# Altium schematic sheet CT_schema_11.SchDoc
size 281 x 153 mm
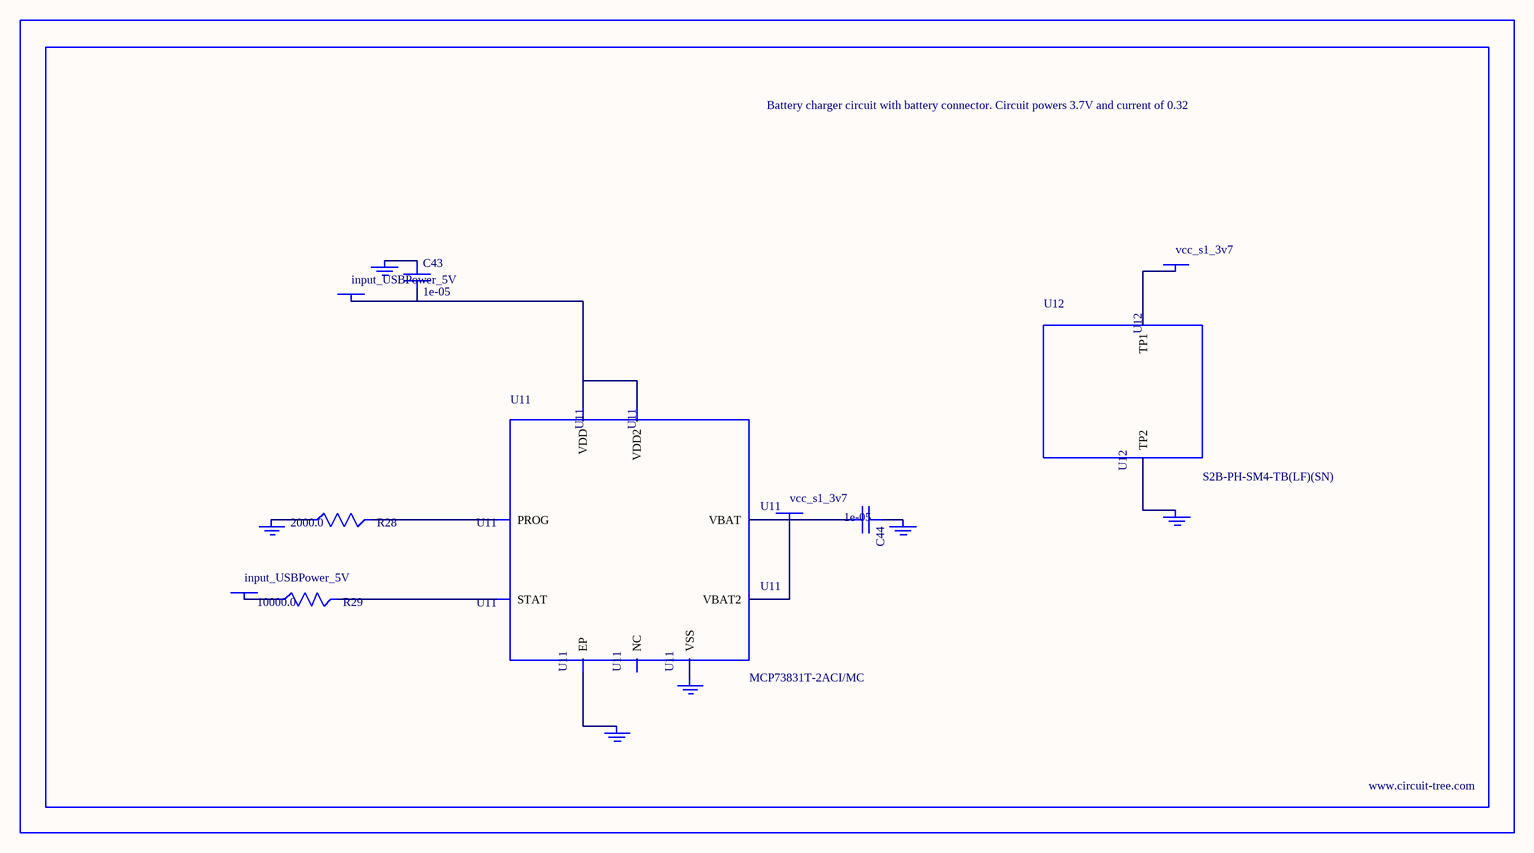
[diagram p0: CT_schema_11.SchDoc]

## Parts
BORDER10  (no value)
C43  1e-05  [C1206]
C44  1e-05  [C1206]
GND_INSTANCE_10_0  (no value)
GND_INSTANCE_10_1  (no value)
GND_INSTANCE_10_2  (no value)
GND_INSTANCE_10_3  (no value)
GND_INSTANCE_10_4  (no value)
GND_INSTANCE_10_5  (no value)
POWER_INSTANCE_10_0  input_USBPower_5V
POWER_INSTANCE_10_1  input_USBPower_5V
POWER_INSTANCE_10_2  vcc_s1_3v7
POWER_INSTANCE_10_3  vcc_s1_3v7
R28  2000.0  [R0603]
R29  10000.0  [R0603]
U11  MCP73831T-2ACI/MC  [DFN8_2X3MC]
U12  S2B-PH-SM4-TB(LF)(SN)  [JST-2-SMD]

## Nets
NetC43_1: C43.1 GND_INSTANCE_10_0.0(GND)
NetC43_2: C43.2 POWER_INSTANCE_10_0.0(PWR) U11.1(VDD) U11.2(VDD2)
NetC44_1: C44.1 GND_INSTANCE_10_1.0(GND)
NetC44_2: C44.2 POWER_INSTANCE_10_2.0(PWR) U11.3(VBAT) U11.4(VBAT2)
NetGND_INSTANCE_10_2_0: GND_INSTANCE_10_2.0(GND) R28.1
NetGND_INSTANCE_10_3_0: GND_INSTANCE_10_3.0(GND) U11.9(EP)
NetGND_INSTANCE_10_4_0: GND_INSTANCE_10_4.0(GND) U11.6(VSS)
NetGND_INSTANCE_10_5_0: GND_INSTANCE_10_5.0(GND) U12.2(TP2)
NetPOWER_INSTANCE_10_1_0: POWER_INSTANCE_10_1.0(PWR) R29.1
NetPOWER_INSTANCE_10_3_0: POWER_INSTANCE_10_3.0(PWR) U12.1(TP1)
NetR28_2: R28.2 U11.8(PROG)
NetR29_2: R29.2 U11.5(STAT)

Not connected (* = marked no-connect by the designer): U11 7(NC)

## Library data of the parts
BORDER10 = BORDER_PAGE10
C43 C44 = C1206C106K3RACTU
GND_INSTANCE_10_0-GND_INSTANCE_10_5 = GND
POWER_INSTANCE_10_0-POWER_INSTANCE_10_3 = PWR
R28 = RC0603JR-072KL
R29 = RC0603JR-0710KL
